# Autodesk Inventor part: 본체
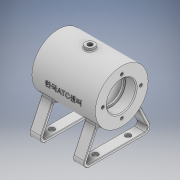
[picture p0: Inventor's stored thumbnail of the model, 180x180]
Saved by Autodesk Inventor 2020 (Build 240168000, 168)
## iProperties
Created: 2021-12
Part Number: 본체
Material: 일반
Document SubType Name: Modeling
Designer: Windows7
Density: 1 g/cm^3
Appearance: 기본값
Author: Windows7
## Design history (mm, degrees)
sketch "스케치1"
  geometry: L1 (-35, 29)-(35, 29); L2 (35, 29)-(35, 0); L3 (35, 0)-(-35, 0); L4 (-35, 0)-(-35, 29); L5 (-35, 16)-(-23, 16); L6 (-23, 16)-(-23, 14); L7 (-23, 14)-(-21, 14); L8 (-21, 14)-(-21, 21); L9 (-21, 21)-(21, 21); L10 (21, 21)-(21, 16); L11 (23, 16)-(23, 16); L12 (23, 16)-(35, 16); L13 (21, 16)-(21, 14); L14 (21, 14)-(23, 14); L15 (23, 14)-(23, 16); 2 further points
  constraints: 30 end point, 10 perpendicular, 4 point on line, 2 collinear, 2 midpoint, 2 parallel, 1 horizontal, 1 vertical, 1 vertical alignment
  dimensions: "d0" = 58 diameter of L1 L3; "d1" = 70 distance of L1.start L1.end; "d2" = 12 distance of L5.start L5.end; "d3" = 12 distance of L11.end L12.end; "d4" = 42 distance of L8.end L9.end; "d5" = 32 diameter of L5 L3; "d6" = 28 diameter of L6.end L3; "d7" = 42 diameter of L9 L3; "d8" = 32 diameter of L12 L3
revolve "회전1" sketch "스케치1" stored, may be unused: angle "d9" = 90 deg
node "작업 평면1"
sketch "스케치2"
  geometry: L1 (-22.743, -17.993)-(-40, -55); L2 (-40, -55)-(0, -55); L3 (0, -55)-(0, -29); L4 (-20.574, -20.438)-(-35.291, -52); L5 (-35.291, -52)-(0, -52); L6 (0, -55)-(0, -52); C1 r 16 at (0, 0) reference; A1 r 29 centre (0, 0) between (-22.743, -17.993) and (0, -29) reference; 1 further point
  constraints: 12 end point, 3 point on circle, 1 collinear, 1 horizontal, 1 perpendicular, 1 point on line, 1 vertical alignment
  dimensions: "d11" = 65 deg angle of L2 L1; "d12" = 3 distance between parallel lines of L1 L4; "d14" = 3 distance between parallel lines of L2 L5; "d15" = 40 distance of L1.end L2.end; "d16" = 55 distance from line of L2 point (0, 0)
extrude "돌출1" join sketch "스케치2" distance "d17" = 12; taper "d18" = 0 deg
fillet "모깎기1" dims "d19" = 6
node "작업 평면2"
sketch "스케치3"
  geometry: C1 r 5 at (0, 0); 1 further point
  constraints: 1 centre point, 1 coincident
  dimensions: "d21" = 10 diameter of C1
extrude "돌출2" join sketch "스케치3" stored distance "d22" = 12; taper "d23" = 0 deg
sketch "스케치5"
  geometry: C1 r 5 at (0, 0) reference; C2 r 5 at (0, 0); 2 further points
  constraints: 2 coincident, 1 centre point
  dimensions: "d70" = 10 diameter of C2
hole "구멍1" sketch "스케치5" at (0, 0) diameter "d24" = 5.1881; stored, may be unused: countersink angle "d28" = 90 deg, drill point angle "d30" = 118 deg; dims "d25" = 6, "d26" = 6, "d27" = 6, "d29" = 8
node "작업 평면3"
sketch "스케치6"
  geometry: L1 (-20.739, 3.002)-(20.739, 3.002); L2 (20.739, 3.002)-(20.739, -3.002); L3 (20.739, -3.002)-(-20.739, -3.002); L4 (-20.739, -3.002)-(-20.739, 3.002); L5 (20.739, -3.002)-(-20.739, 3.002); L6 (20.739, 3.002)-(-20.739, -3.002); L7 (-35, -29)-(-35, 29) reference; L8 (-35, 29)-(35, 29) reference; 2 further points
  constraints: 4 end point, 1 midpoint, 2 other
  dimensions: "d32" = 35 distance from line of L7 point (0, 0); "d33" = 29 distance from line of point (0, 0) L8
feature "엠보싱1" sketch "스케치6" dims "d0" = 58, "d1" = 70, "d2" = 12, "d3" = 12, "d4" = 42, "d5" = 32, "d6" = 28, "d7" = 42, "d8" = 32, "d11" = 65 deg, "d34" = 0.5, "d35" = 0
sketch "스케치7"
  geometry: L1 (-42, 17.291)-(6, 17.291); L2 (6, 17.291)-(6, 53.291); L3 (6, 53.291)-(-42, 53.291); L4 (-42, 53.291)-(-42, 17.291); L5 (-48, 4.709)-(-48, 65.873) reference; 6 further points
  constraints: 8 end point, 4 coincident, 2 parallel, 1 horizontal, 1 horizontal alignment, 1 midpoint, 1 perpendicular
  dimensions: "d36" = 48 distance of L2.end L3.end; "d37" = 6 distance between parallel lines of L5 L4; "d38" = 36 distance between parallel lines of L1 L3
hole "구멍2" sketch "스케치7" at (-42, 53.291), (6, 53.291), (6, 17.291), (-42, 17.291) diameter "d39" = 6; stored, may be unused: countersink angle "d43" = 90 deg, drill point angle "d45" = 0 deg; dims "d40" = 8, "d41" = 6, "d42" = 6, "d44" = 8.8
sketch "스케치8" dims "d46" = 42
  geometry: L1 (0, 0)-(0, 43.275); 2 further points
  constraints: 2 end point, 1 coincident, 1 point on line, 1 vertical, 1 vertical alignment, 2 other
hole "구멍3" sketch "스케치8" at (0, 21) diameter "d47" = 3.242; stored, may be unused: countersink angle "d51" = 90 deg, drill point angle "d53" = 118 deg; dims "d48" = 8, "d49" = 6, "d50" = 6, "d52" = 10
sketch "스케치9"
  geometry: L1 (0, 0)-(-43.535, 0); L2 (0, 0)-(-30.07, -10.945)
  constraints: 4 end point, 1 horizontal
  dimensions: "d57" = 32 distance of L1.start L2.end; "d58" = 20 deg angle of L2 L1
node "작업 평면4"
sketch "스케치10"
  geometry: C1 r 6 at (0, 0); 2 further points
  constraints: 1 centre point, 1 coincident
  dimensions: "d59" = 12 diameter of C1
extrude "돌출3" join sketch "스케치10" stored distance "d60" = 12; taper "d61" = 0 deg
sketch "스케치11"
  geometry: C1 r 6 at (0, 0) reference; 2 further points
  constraints: 1 coincident
hole "구멍4" sketch "스케치11" at (0, 0) diameter "d62" = 5.1881; stored, may be unused: countersink angle "d66" = 90 deg, drill point angle "d68" = 0 deg; dims "d63" = 12, "d64" = 6, "d65" = 6, "d67" = 16
fillet "모깎기2" dims "d69" = 1
fillet "모깎기3" dims "d71" = 0.3
chamfer "모따기1" distance "d72" = 1; stored, may be unused: second distance "d73" = 2, angle "d74" = 45 deg
fillet "모깎기4" dims "d75" = 3
fillet "모깎기5" dims "d76" = 3
fillet "모깎기6" dims "d77" = 0.5
fillet "모깎기7" dims "d78" = 3
sketch "스케치13"
  geometry: L1 (18, -54.5)-(18, -52.5) reference; L2 (18.5, -52)-(29.5, -52) reference; L3 (30, -52.5)-(30, -54.5) reference; L4 (29.5, -55)-(18.5, -55) reference; L5 (-30, -54.5)-(-30, -52.5) reference; L6 (-29.5, -52)-(-18.5, -52) reference; L7 (-18, -52.5)-(-18, -54.5) reference; L8 (-18.5, -55)-(-29.5, -55) reference; L9 (24.026, -21)-(25, -22.621) reference; L10 (25, -22.621)-(35, -22.621) reference; L11 (35, -22.621)-(35, -29) reference; L12 (35, -29)-(-35, -29) reference; L13 (-35, -29)-(-35, -22.621) reference; L14 (-35, -22.621)-(-25, -22.621) reference; L15 (-25, -22.621)-(-24.026, -21) reference; L16 (-24.026, -21)-(-25, -19.379) reference; L17 (-25, -19.379)-(-35, -19.379) reference; L18 (-35, -19.379)-(-35, -17) reference; L19 (-35, -17)-(-34, -16) reference; L20 (-34, -16)-(-23.3, -16) reference; L21 (-23, -15.7)-(-23, -14) reference; L22 (-23, -14)-(-21, -14) reference; L23 (-21, -14)-(-21, -18) reference; L24 (-18, -21)-(18, -21) reference; L25 (21, -18)-(21, -14) reference; L26 (21, -14)-(23, -14) reference; L27 (23, -14)-(23, -15.7) reference; L28 (23.3, -16)-(34, -16) reference; L29 (34, -16)-(35, -17) reference; L30 (35, -17)-(35, -19.379) reference; L31 (35, -19.379)-(25, -19.379) reference; L32 (25, -19.379)-(24.026, -21) reference; L33 (25, 22.621)-(24.026, 21) reference; L34 (24.026, 21)-(25, 19.379) reference; L35 (25, 19.379)-(35, 19.379) reference; L36 (35, 19.379)-(35, 17) reference; L37 (35, 17)-(34, 16) reference; L38 (34, 16)-(23.3, 16) reference; L39 (23, 15.7)-(23, 14) reference; L40 (23, 14)-(21, 14) reference; L41 (21, 14)-(21, 18) reference; L42 (18, 21)-(-18, 21) reference; L43 (-21, 18)-(-21, 14) reference; L44 (-21, 14)-(-23, 14) reference; L45 (-23, 14)-(-23, 15.7) reference; L46 (-23.3, 16)-(-34, 16) reference; L47 (-34, 16)-(-35, 17) reference; L48 (-35, 17)-(-35, 19.379) reference; L49 (-35, 19.379)-(-25, 19.379) reference; L50 (-25, 19.379)-(-24.026, 21) reference; L51 (-24.026, 21)-(-25, 22.621) reference; L52 (-25, 22.621)-(-35, 22.621) reference; L53 (-35, 22.621)-(-35, 29) reference; L54 (-35, 29)-(-6, 29) reference; L55 (-5, 30)-(-5, 32) reference; L56 (-5, 32)-(-2.594, 32) reference; L57 (-2.594, 32)-(-2.594, 24) reference; L58 (-2.594, 24)-(0, 22.441) reference; L59 (0, 22.441)-(2.594, 24) reference; L60 (2.594, 24)-(2.594, 32) reference; L61 (2.594, 32)-(5, 32) reference; L62 (5, 32)-(5, 30) reference; L63 (6, 29)-(35, 29) reference; L64 (35, 29)-(35, 22.621) reference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; A1 r 0.5 centre (18.5, -52.5) between (18.5, -52) and (18, -52.5) reference; A2 r 0.5 centre (29.5, -52.5) between (30, -52.5) and (29.5, -52) reference; A3 r 0.5 centre (29.5, -54.5) between (29.5, -55) and (30, -54.5) reference; A4 r 0.5 centre (18.5, -54.5) between (18, -54.5) and (18.5, -55) reference; A5 r 0.5 centre (-29.5, -52.5) between (-29.5, -52) and (-30, -52.5) reference; A6 r 0.5 centre (-18.5, -52.5) between (-18, -52.5) and (-18.5, -52) reference; A7 r 0.5 centre (-18.5, -54.5) between (-18.5, -55) and (-18, -54.5) reference; A8 r 0.5 centre (-29.5, -54.5) between (-30, -54.5) and (-29.5, -55) reference; A9 r 0.3 centre (-23.3, -15.7) between (-23.3, -16) and (-23, -15.7) reference; A10 r 3 centre (-18, -18) between (-21, -18) and (-18, -21) reference; A11 r 3 centre (18, -18) between (18, -21) and (21, -18) reference; A12 r 0.3 centre (23.3, -15.7) between (23, -15.7) and (23.3, -16) reference; A13 r 0.3 centre (23.3, 15.7) between (23.3, 16) and (23, 15.7) reference; A14 r 3 centre (18, 18) between (21, 18) and (18, 21) reference; A15 r 3 centre (-18, 18) between (-18, 21) and (-21, 18) reference; A16 r 0.3 centre (-23.3, 15.7) between (-23, 15.7) and (-23.3, 16) reference; 2 further points
  constraints: 8 end point, 2 parallel, 1 horizontal, 1 midpoint, 1 perpendicular, 1 point on line, 2 other
  dimensions: "d79" = 1.5 distance of L67.end L68.end
revolve "회전2" sketch "스케치13" stored, may be unused: angle "d80" = 90 deg
fillet "모깎기8" dims "d81" = 1
node "솔리드1"
mirror "미러1"
mirror "미러2"
pattern_circular "원형 패턴1" dims angle "d55" = 360 deg
mirror "미러3"
node "절단 모서리 투영1"
node "절단 모서리 투영2"
feature "A9D066F2-1C7D-4E18-AEED-F7BC21143FA4" dims "d39" = 6, "d40" = 8, "d41" = 6, "d42" = 6, "d43" = 90 deg, "d44" = 8.8, "d45" = 0
other parameters: "d10" = -5, "d20" = 32, "d31" = 47
